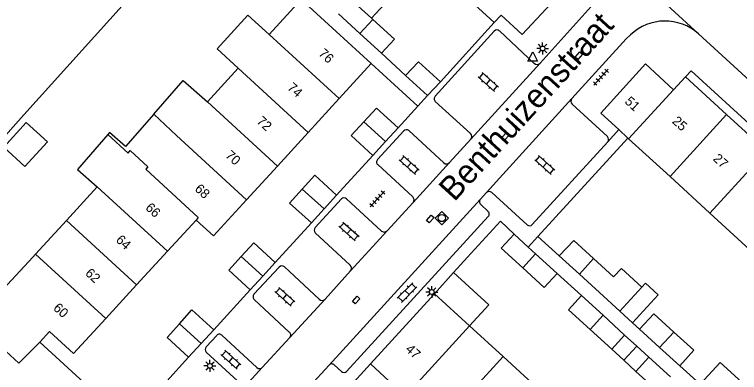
# Model space of a CAD drawing. Extents: x 128000 to 131008, y 398996 to 402500.
# Drawn here: x 129021.3 to 129097.6, y 399487.9 to 399525.5 of the extents above; entities that cross this region are included whole.
import ezdxf

# ---------------------------------------------------------------- set-up
doc = ezdxf.new("R2010")
doc.units = 0
for name, color, linetype in [('gg-afsc-erfafscheiding', 7, 'Continuous'), ('gg-afsc-muur', 7, 'Continuous'), ('gg-anno-huisnummerreeks BGT', 7, 'Continuous'), ('gg-anno-openbare ruimte label', 7, 'Continuous'), ('gg-bbg-bijgebouw', 7, 'Continuous'), ('gg-bbg-gedigitaliseerde bebouwing', 7, 'Continuous'), ('gg-bbg-gedigitaliseerde bijgebouw', 7, 'Continuous'), ('gg-bbg-hoofdgebouw', 7, 'Continuous'), ('gg-bbg-luifel en loopbrug', 7, 'Continuous'), ('gg-bbg-tussenscheiding', 7, 'Continuous'), ('gg-knt-verharding', 7, 'Continuous'), ('gg-knt-verharding nz', 7, 'Continuous'), ('gg-kntw-beschoeiing', 7, 'Continuous'), ('gt-grn-weggrens', 7, 'Continuous'), ('gt-symb-klinker verharding', 7, 'Continuous'), ('gt-symb-kolk center center', 7, 'Continuous'), ('gt-symb-lichtmast', 7, 'Continuous'), ('gt-symb-rioolschacht', 7, 'Continuous'), ('gt-symb-tegel verharding', 7, 'Continuous'), ('gt-symb-waterafsluiter', 7, 'Continuous')]:
    doc.layers.add(name, color=color, linetype=linetype)

# ---------------------------------------------------------------- blocks, each defined once
blk = doc.blocks.new('gt0-LMAST')
at = {"layer": 'gt-symb-lichtmast'}
for p, q in [((-0.182, 0.173), (-0.447, 0.438)), ((-0.005, 0.246), (-0.005, 0.621)), ((0.172, 0.173), (0.437, 0.438)), ((-0.255, -0.004), (-0.63, -0.004)), ((-0.182, -0.181), (-0.447, -0.446)), ((-0.005, -0.254), (-0.005, -0.629)), ((0.437, -0.446), (0.172, -0.181)), ((0.245, -0.004), (0.62, -0.004))]:
    blk.add_line(p, q, dxfattribs=at)
blk.add_circle((-0.005, -0.004), 0.25, dxfattribs=at)
blk = doc.blocks.new('gt0-KL1')
at = {"layer": 'gt-symb-klinker verharding'}
for p, q in [((-1.15, 0.3), (1.15, 0.3)), ((-1, -0.3), (-1, 0.3)), ((-0.5, 0.3), (-0.5, 0.45)), ((0, -0.3), (0, 0.3)), ((0.5, 0.3), (0.5, 0.45)), ((1, -0.3), (1, 0.3)), ((-1.15, -0.3), (1.15, -0.3)), ((-0.5, -0.45), (-0.5, -0.3)), ((0.5, -0.45), (0.5, -0.3))]:
    blk.add_line(p, q, dxfattribs=at)
blk = doc.blocks.new('gt0-WAFSL')
at = {"layer": 'gt-symb-waterafsluiter'}
for p, q in [((-0.5, -0.333), (0, 0.667)), ((0, 0.667), (0.5, -0.333)), ((0.5, -0.333), (-0.5, -0.333))]:
    blk.add_line(p, q, dxfattribs=at)
blk = doc.blocks.new('gt0-KOLKCC')
at = {"layer": 'gt-symb-kolk center center'}
blk.add_lwpolyline([(-0.375, 0.2), (0.375, 0.2), (0.375, -0.2), (-0.375, -0.2)], close=True, dxfattribs=at)
blk = doc.blocks.new('gt0-TEG1')
at = {"layer": 'gt-symb-tegel verharding'}
for p, q in [((-1.125, 0), (1.125, 0)), ((-0.9, -0.25), (-0.9, 0.25)), ((-0.45, -0.25), (-0.45, 0.25)), ((0, -0.25), (0, 0.25)), ((0.45, -0.25), (0.45, 0.25)), ((0.9, -0.25), (0.9, 0.25))]:
    blk.add_line(p, q, dxfattribs=at)
blk = doc.blocks.new('gt0-RS')
at = {"layer": 'gt-symb-rioolschacht'}
blk.add_lwpolyline([(-0.5, -0.5), (0.5, -0.5), (0.5, 0.5), (-0.5, 0.5)], close=True, dxfattribs=at)
blk.add_circle((0, 0), 0.375, dxfattribs=at)

msp = doc.modelspace()

# ---------------------------------------------------------------- linework, layer by layer
at = {"layer": 'gg-afsc-erfafscheiding'}
for p, q in [((129062.46, 399519.11), (129059.91, 399521.45)), ((129058.85, 399520.36), (129063.746, 399515.863)), ((129076.365, 399502.197), (129085.82, 399512.53)), ((129078.6, 399500.15), (129076.365, 399502.197)), ((129078.39, 399498.31), (129080.95, 399495.97)), ((129086.309, 399493.115), (129087.05, 399492.44)), ((129091.27, 399488.59), (129093.41, 399486.651))]:
    msp.add_line(p, q, dxfattribs=at)
at = {"layer": 'gg-afsc-muur'}
for p, q in [((129071.78, 399524.66), (129066.13, 399518.44)), ((129068.972, 399500), (129067.504, 399498.39))]:
    msp.add_line(p, q, dxfattribs=at)
msp.add_lwpolyline([(129068.972, 399500), (129072.43, 399503.78), (129073.86, 399502.43)], dxfattribs=at)
at = {"layer": 'gg-bbg-bijgebouw'}
for p, q in [((129062.46, 399519.11), (129064.77, 399516.99)), ((129066.13, 399518.44), (129064.77, 399516.99)), ((129061.69, 399513.6), (129060.36, 399512.15)), ((129060.36, 399512.15), (129059.031, 399510.7)), ((129055.21, 399506.52), (129053.897, 399505.073)), ((129053.897, 399505.073), (129052.56, 399503.6)), ((129073.86, 399502.43), (129072.5, 399500.96)), ((129073.86, 399502.43), (129075.332, 399501.068)), ((129080.13, 399501.76), (129078.6, 399500.15)), ((129047.438, 399498.022), (129048.751, 399499.46)), ((129046.13, 399496.59), (129047.438, 399498.022)), ((129042.29, 399492.39), (129040.97, 399490.95)), ((129040.97, 399490.95), (129039.65, 399489.51))]:
    msp.add_line(p, q, dxfattribs=at)
for points in [[(129066.13, 399518.44), (129063.83, 399520.55), (129062.46, 399519.11)], [(129058.078, 399514.232), (129059.41, 399515.68), (129061.69, 399513.6)], [(129059.031, 399510.7), (129056.75, 399512.79), (129058.078, 399514.232)], [(129051.603, 399507.157), (129052.931, 399508.61), (129055.21, 399506.52)], [(129052.56, 399503.6), (129050.27, 399505.7), (129051.603, 399507.157)], [(129045.185, 399500.085), (129046.5, 399501.52), (129048.751, 399499.46)], [(129046.13, 399496.59), (129043.87, 399498.65), (129045.185, 399500.085)], [(129038.691, 399493.01), (129040.001, 399494.46), (129042.29, 399492.39)], [(129039.65, 399489.51), (129037.38, 399491.56), (129038.691, 399493.01)]]:
    msp.add_lwpolyline(points, dxfattribs=at)
at = {"layer": 'gg-bbg-gedigitaliseerde bebouwing'}
for p, q in [((129068.099, 399528.039), (129071.78, 399524.66)), ((129051.488, 399527.122), (129048.101, 399523.419)), ((129058.85, 399520.36), (129051.488, 399527.122)), ((129044.862, 399519.878), (129041.63, 399516.344)), ((129030.048, 399507.411), (129026.797, 399503.862)), ((129026.797, 399503.862), (129023.569, 399500.34)), ((129020.17, 399496.63), (129023.258, 399500)), ((129023.569, 399500.34), (129023.258, 399500))]:
    msp.add_line(p, q, dxfattribs=at)
for points in [[(129044.862, 399519.878), (129042.648, 399521.903), (129045.887, 399525.444), (129048.101, 399523.419)], [(129035.988, 399515.02), (129039.075, 399518.567), (129041.63, 399516.344)], [(129035.988, 399515.02), (129033.032, 399511.624), (129031.345, 399513.093), (129031.174, 399512.897)], [(129031.174, 399512.897), (129027.972, 399509.218), (129030.048, 399507.411)]]:
    msp.add_lwpolyline(points, dxfattribs=at)
at = {"layer": 'gg-bbg-gedigitaliseerde bijgebouw'}
for p, q in [((129058.875, 399525.108), (129056.77, 399527.04)), ((129055.41, 399525.57), (129057.66, 399523.5)), ((129059.022, 399524.973), (129058.875, 399525.108)), ((129057.66, 399523.5), (129059.91, 399521.45)), ((129080.13, 399501.76), (129082.218, 399499.855)), ((129074.772, 399498.882), (129072.5, 399500.96)), ((129076.11, 399500.348), (129075.332, 399501.068)), ((129078.39, 399498.31), (129076.11, 399500.348)), ((129080.721, 399498.217), (129078.6, 399500.15)), ((129084.32, 399497.93), (129082.218, 399499.855)), ((129080.721, 399498.217), (129082.83, 399496.3)), ((129084.978, 399494.327), (129087.299, 399496.854)), ((129080.95, 399495.97), (129083.218, 399493.898)), ((129082.83, 399496.3), (129084.978, 399494.327)), ((129083.218, 399493.898), (129085.48, 399491.83)), ((129084.12, 399490.34), (129081.86, 399492.4)), ((129089.165, 399490.511), (129087.05, 399492.44)), ((129085.48, 399491.83), (129084.12, 399490.34)), ((129091.27, 399488.59), (129089.165, 399490.511)), ((129086.67, 399488.01), (129088.04, 399489.5)), ((129088.04, 399489.5), (129090.303, 399487.432)), ((129088.94, 399485.94), (129086.67, 399488.01))]:
    msp.add_line(p, q, dxfattribs=at)
for points in [[(129059.91, 399521.45), (129061.28, 399522.9), (129059.022, 399524.973)], [(129078.39, 399498.31), (129077.03, 399496.81), (129074.772, 399498.882)], [(129087.299, 399496.854), (129085.147, 399498.83), (129084.32, 399497.93)], [(129081.86, 399492.4), (129079.59, 399494.47), (129080.95, 399495.97)], [(129087.05, 399492.44), (129088.54, 399494.07), (129090.647, 399492.143)], [(129090.647, 399492.143), (129092.75, 399490.22), (129091.27, 399488.59)], [(129099.085, 399484.431), (129099.712, 399485.114), (129095.528, 399488.956), (129093.41, 399486.651)]]:
    msp.add_lwpolyline(points, dxfattribs=at)
at = {"layer": 'gg-bbg-hoofdgebouw'}
for p, q in [((129058.85, 399520.36), (129055.477, 399516.673)), ((129090.62, 399517.6), (129091.87, 399518.95)), ((129091.87, 399518.95), (129096.19, 399514.991)), ((129055.477, 399516.673), (129052.226, 399513.121)), ((129096.19, 399514.991), (129100.391, 399511.142)), ((129052.226, 399513.121), (129048.988, 399509.582)), ((129085.82, 399512.53), (129084.862, 399513.407)), ((129085.898, 399512.459), (129085.82, 399512.53)), ((129090.252, 399508.472), (129085.898, 399512.459)), ((129048.988, 399509.582), (129045.739, 399506.031)), ((129094.443, 399504.634), (129090.252, 399508.472)), ((129098.651, 399500.781), (129094.443, 399504.634)), ((129040.431, 399503.91), (129037.422, 399500.638)), ((129034.17, 399497.1), (129037.422, 399500.638)), ((129030.932, 399493.578), (129034.17, 399497.1)), ((129058.755, 399488.795), (129065.48, 399496.17)), ((129065.48, 399496.17), (129069.174, 399492.794)), ((129027.55, 399489.9), (129030.932, 399493.578)), ((129069.174, 399492.794), (129072.711, 399489.561)), ((129024.008, 399491.079), (129030.226, 399485.396)), ((129072.711, 399489.561), (129076.259, 399486.319)), ((129062.445, 399485.425), (129058.755, 399488.795))]:
    msp.add_line(p, q, dxfattribs=at)
for points in [[(129078.58, 399532.04), (129076.55, 399529.83), (129078.79, 399527.781), (129074.71, 399523.39), (129072.501, 399525.44), (129071.78, 399524.66)], [(129090.62, 399517.6), (129087.66, 399520.33), (129082.97, 399515.14), (129084.862, 399513.407)], [(129045.739, 399506.031), (129042.27, 399502.24), (129040.431, 399503.91)], [(129027.55, 399489.9), (129025.04, 399492.208), (129024.008, 399491.079)]]:
    msp.add_lwpolyline(points, dxfattribs=at)
at = {"layer": 'gg-bbg-luifel en loopbrug'}
for p, q in [((129067.504, 399498.39), (129065.48, 399496.17)), ((129084.978, 399494.327), (129086.309, 399493.115)), ((129085.48, 399491.83), (129086.76, 399490.665)), ((129085.395, 399489.175), (129086.76, 399490.665)), ((129086.76, 399490.665), (129088.04, 399489.5)), ((129084.12, 399490.34), (129085.395, 399489.175)), ((129085.395, 399489.175), (129086.67, 399488.01))]:
    msp.add_line(p, q, dxfattribs=at)
for points in [[(129058.875, 399525.108), (129060.23, 399526.579), (129058.129, 399528.515), (129056.77, 399527.04)], [(129020.227, 399511.56), (129022.589, 399514.142), (129024.802, 399512.117), (129022.44, 399509.535), (129020.227, 399511.56)], [(129069.174, 399492.794), (129071.2, 399495.007), (129067.504, 399498.39)], [(129086.309, 399493.115), (129089.009, 399496.055), (129087.684, 399497.273), (129087.299, 399496.854)]]:
    msp.add_lwpolyline(points, dxfattribs=at)
at = {"layer": 'gg-bbg-tussenscheiding'}
for p, q in [((129059.022, 399524.973), (129057.66, 399523.5)), ((129048.101, 399523.419), (129055.477, 399516.673)), ((129044.862, 399519.878), (129052.226, 399513.121)), ((129085.898, 399512.459), (129090.62, 399517.6)), ((129041.63, 399516.344), (129048.988, 399509.582)), ((129038.391, 399512.804), (129035.988, 399515.02)), ((129096.19, 399514.991), (129090.252, 399508.472)), ((129058.078, 399514.232), (129060.36, 399512.15)), ((129038.391, 399512.804), (129045.739, 399506.031)), ((129100.391, 399511.142), (129094.443, 399504.634)), ((129030.048, 399507.411), (129037.422, 399500.638)), ((129051.603, 399507.157), (129053.897, 399505.073)), ((129026.797, 399503.862), (129034.17, 399497.1)), ((129030.932, 399493.578), (129023.569, 399500.34)), ((129047.438, 399498.022), (129045.185, 399500.085)), ((129074.772, 399498.882), (129076.11, 399500.348)), ((129080.721, 399498.217), (129082.218, 399499.855)), ((129083.218, 399493.898), (129081.86, 399492.4)), ((129038.691, 399493.01), (129040.97, 399490.95)), ((129062.445, 399485.425), (129069.174, 399492.794)), ((129089.165, 399490.511), (129090.647, 399492.143)), ((129065.988, 399482.189), (129072.711, 399489.561))]:
    msp.add_line(p, q, dxfattribs=at)
for points in [[(129031.174, 399512.897), (129033.29, 399510.95), (129033.52, 399511.2), (129035.379, 399509.511)], [(129035.379, 399509.511), (129035.15, 399509.26), (129040.66, 399504.18), (129040.431, 399503.91)], [(129024.008, 399491.079), (129021.806, 399488.864), (129020.44, 399490.12)]]:
    msp.add_lwpolyline(points, dxfattribs=at)
at = {"layer": 'gg-knt-verharding'}
for p, q in [((129076.599, 399520.395), (129081.973, 399526.336)), ((129065.568, 399516.933), (129071.777, 399523.768)), ((129072.312, 399523.78), (129075.977, 399520.376)), ((129079.945, 399516.68), (129085.66, 399522.957)), ((129085.66, 399522.957), (129086.107, 399523.362)), ((129092.47, 399519.6), (129091.87, 399518.95)), ((129092.47, 399519.6), (129126.72, 399488.21)), ((129063.746, 399515.863), (129061.69, 399513.6)), ((129069.276, 399512.986), (129065.582, 399516.374)), ((129079.979, 399516.078), (129083.679, 399512.679)), ((129059.516, 399510.265), (129062.265, 399513.287)), ((129062.797, 399513.314), (129066.463, 399509.909)), ((129067.089, 399509.948), (129069.328, 399512.403)), ((129083.704, 399512.142), (129075.772, 399503.437)), ((129059.031, 399510.7), (129055.21, 399506.52)), ((129063.205, 399506.338), (129059.532, 399509.731)), ((129070.957, 399506.806), (129070.314, 399506.078)), ((129071.535, 399506.805), (129075.235, 399503.406)), ((129052.944, 399503.123), (129055.705, 399506.133)), ((129060.51, 399502.76), (129063.25, 399505.763)), ((129070.368, 399505.527), (129071.096, 399504.839)), ((129052.56, 399503.6), (129048.751, 399499.46)), ((129071.146, 399504.296), (129056.259, 399488.006)), ((129056.638, 399499.161), (129052.965, 399502.56)), ((129046.523, 399496.109), (129049.17, 399498.972)), ((129049.713, 399498.99), (129053.38, 399495.579)), ((129053.988, 399495.602), (129056.683, 399498.574)), ((129046.13, 399496.59), (129042.29, 399492.39)), ((129050.234, 399492.14), (129046.574, 399495.537)), ((129041.493, 399490.589), (129042.605, 399491.789)), ((129043.149, 399491.818), (129046.827, 399488.405)), ((129047.394, 399488.413), (129050.291, 399491.585)), ((129045.199, 399486.639), (129041.507, 399490.029)), ((129039.65, 399489.51), (129037.35, 399486.989)), ((129054.428, 399488.676), (129052.36, 399486.43)), ((129055.713, 399487.993), (129054.983, 399488.669)), ((129055.6, 399485.32), (129058.755, 399488.795))]:
    msp.add_line(p, q, dxfattribs=at)
for points in [[(129093.257, 399523.479), (129118.904, 399500), (129122.503, 399496.685)], [(129056.256, 399506.139), (129059.923, 399502.734), (129060.201, 399502.626), (129060.51, 399502.76)]]:
    msp.add_lwpolyline(points, dxfattribs=at)
for centre, radius, start, end in [((129089.745, 399519.558), 5.264, 48.15255, 133.72242), ((129072.05, 399523.507), 0.378, 46.19417, 136.37568), ((129076.278, 399520.723), 0.459, 229.05779, 314.44151), ((129065.84, 399516.66), 0.385, 134.93887, 227.93044), ((129080.272, 399516.397), 0.433, 139.10356, 227.36152), ((129062.546, 399513.007), 0.396, 50.7014, 135.10935), ((129069, 399512.668), 0.421, 321.07938, 49.11451), ((129083.406, 399512.397), 0.392, 319.43345, 45.8975), ((129059.738, 399510.004), 0.343, 130.46503, 232.9674), ((129066.755, 399510.267), 0.462, 230.7892, 316.34068), ((129071.245, 399506.449), 0.459, 50.84222, 128.95953), ((129055.984, 399505.815), 0.423, 49.97918, 131.2686), ((129062.935, 399506.028), 0.412, 320.00753, 48.94226), ((129070.62, 399505.83), 0.394, 140.97925, 230.21539), ((129070.891, 399504.546), 0.357, 315.47332, 55.04872), ((129053.281, 399502.854), 0.431, 141.36625, 222.90605), ((129075.487, 399503.704), 0.39, 229.71814, 316.88968), ((129049.451, 399498.687), 0.401, 49.20464, 134.59258), ((129056.349, 399498.844), 0.43, 321.12019, 47.64736), ((129046.812, 399495.846), 0.39, 137.74502, 232.44511), ((129053.672, 399495.899), 0.434, 227.60798, 316.72483), ((129042.891, 399491.541), 0.379, 47.05752, 139.04545), ((129049.99, 399491.835), 0.391, 320.3331, 51.39464), ((129041.801, 399490.317), 0.411, 138.51452, 224.34968), ((129047.106, 399488.705), 0.41, 226.99714, 314.61956), ((129054.702, 399488.404), 0.386, 43.37943, 135.17534), ((129055.979, 399488.289), 0.398, 228.0015, 314.72636)]:
    msp.add_arc(centre, radius, start, end, dxfattribs=at)
at = {"layer": 'gg-knt-verharding nz'}
for p, q in [((129069.328, 399512.403), (129076.599, 399520.395)), ((129079.945, 399516.68), (129070.957, 399506.806)), ((129063.25, 399505.763), (129067.089, 399509.948)), ((129070.314, 399506.078), (129054.428, 399488.676)), ((129056.683, 399498.574), (129060.51, 399502.76)), ((129050.291, 399491.585), (129053.988, 399495.602)), ((129045.235, 399486.072), (129047.394, 399488.413))]:
    msp.add_line(p, q, dxfattribs=at)
at = {"layer": 'gg-kntw-beschoeiing'}
msp.add_line((129008.973, 399500), (129022.333, 399514.972), dxfattribs=at)
msp.add_lwpolyline([(129022.333, 399514.972), (129034.28, 399528.254), (129034.165, 399532.102), (129036.526, 399534.639), (129044.201, 399543.199)], dxfattribs=at)
at = {"layer": 'gt-grn-weggrens'}
for p, q in [((129081.937, 399533.842), (129093.257, 399523.479)), ((129063.746, 399515.863), (129064.77, 399516.99)), ((129084.862, 399513.407), (129083.704, 399512.142)), ((129076.365, 399502.197), (129075.332, 399501.068))]:
    msp.add_line(p, q, dxfattribs=at)

# ---------------------------------------------------------------- block references
at = {"layer": 'gt-symb-klinker verharding'}
for p, rotation in [((129071.155, 399518.413), -41.83814925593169), ((129062.84, 399509.703), -41.83814925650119), ((129077.094, 399509.703), -41.83814925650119), ((129056.505, 399502.708), -41.83814925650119), ((129049.774, 399495.845), -41.838149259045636), ((129062.608, 399496.29), 45.32415936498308), ((129044.099, 399489.246), -41.83814925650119)]:
    msp.add_blockref('gt0-KL1', p, dxfattribs=dict(at, rotation=rotation))
at = {"layer": 'gt-symb-kolk center center'}
for p, rotation in [((129080.666, 399521.184), -132.20433768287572), ((129072.977, 399512.708), -132.3661698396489), ((129065.05, 399504.019), -132.4471018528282), ((129057.262, 399495.502), 47.552898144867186)]:
    msp.add_blockref('gt0-KOLKCC', p, dxfattribs=dict(at, rotation=rotation))
at = {"layer": 'gt-symb-lichtmast'}
for p in [(129076.867, 399521.939), (129065.211, 399496.351), (129041.895, 399488.586)]:
    msp.add_blockref('gt0-LMAST', p, dxfattribs=at)
at = {"layer": 'gt-symb-rioolschacht', "rotation": 45.48623256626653}
msp.add_blockref('gt0-RS', (129066.268, 399504.115), dxfattribs=at)
at = {"layer": 'gt-symb-tegel verharding', "rotation": 47.91906958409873}
for p in [(129082.982, 399518.925), (129059.49, 399506.123)]:
    msp.add_blockref('gt0-TEG1', p, dxfattribs=at)
at = {"layer": 'gt-symb-waterafsluiter'}
msp.add_blockref('gt0-WAFSL', (129075.819, 399520.921), dxfattribs=at)

# ---------------------------------------------------------------- texts
at = {"layer": 'gg-anno-huisnummerreeks BGT'}
for s, rotation, p in [('76', 317.6, (129053.241, 399521.305)), ('74', 317.6, (129049.954, 399517.713)), ('51', 317.3, (129085.426, 399516.268)), ('72', 317.6, (129046.73, 399514.191)), ('25', 317.5, (129090.403, 399514.191)), ('70', 317.6, (129043.441, 399510.595)), ('27', 317.5, (129094.693, 399510.26)), ('68', 317.6, (129040.219, 399507.075)), ('66', 317.4, (129035.035, 399505.099)), ('64', 317.4, (129031.929, 399501.72)), ('62', 317.4, (129028.707, 399498.215)), ('60', 317.4, (129025.35, 399494.564)), ('47', 317.6, (129062.37, 399490.234))]:
    msp.add_text(s, height=1, rotation=rotation, dxfattribs=at).set_placement(p)
at = {"layer": 'gg-anno-openbare ruimte label'}
msp.add_text('Benthuizenstraat', height=2.5, rotation=47.6, dxfattribs=at).set_placement((129067.574, 399505.755))

doc.saveas('drawing.dxf')
